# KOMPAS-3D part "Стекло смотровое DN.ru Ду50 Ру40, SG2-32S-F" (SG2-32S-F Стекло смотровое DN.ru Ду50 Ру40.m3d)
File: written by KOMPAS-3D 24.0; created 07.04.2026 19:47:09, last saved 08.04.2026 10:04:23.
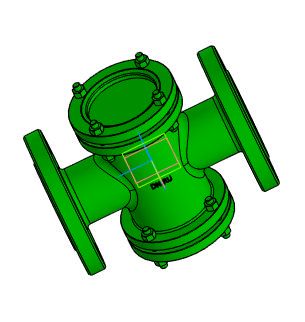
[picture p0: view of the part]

Document properties: Автор: Main; Полное имя файла: SG2-34G-FСтекло смотровое DN.ru Ду50 Ру40 (3d).cdw

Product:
- Body: Тело 1  | qty 1
    Масса: 11.518228
- Part/product: Стекло смотровое DN.ru Ду50 Ру40  | designation SG2-32S-F
    Масса: 10.5
    Раздел спецификации: Прочие изделия
    Форматы листов документа: A4
    Примечание: D500-00108

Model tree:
1. Операция без истории:1

Expressions: SG2-32S-F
